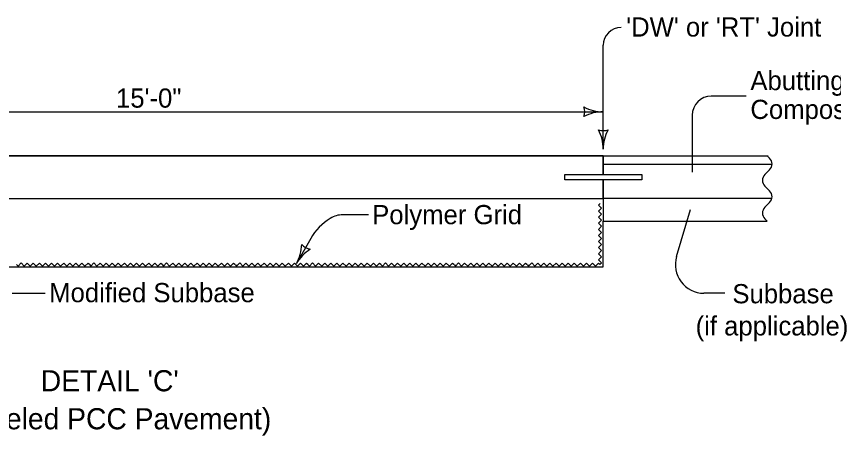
# Model space of a CAD drawing. Extents: x 8925 to 81668, y 4369 to 11918.
# Drawn here: x 14998 to 15849, y 9007 to 9444 of the extents above; entities that cross this region are included whole.
import ezdxf

# ---------------------------------------------------------------- set-up
doc = ezdxf.new("R2010")
doc.units = 0
doc.layers.add('dsnShtPlotShapeBatchPrint', color=7, linetype='Continuous')
doc.layers.add('dsnStdBorder', color=7, linetype='Continuous')

msp = doc.modelspace()

# ---------------------------------------------------------------- linework, layer by layer
at = {"layer": 'dsnStdBorder'}
for p, q in [((15609.52, 9305.72), (15609.52, 9413.92)), ((15758.5, 9360.95), (15722.03, 9360.95)), ((14682.88, 9344.69), (15609.52, 9344.69)), ((15702.23, 9341.15), (15702.23, 9281.87)), ((14693.03, 9298.93), (15609.52, 9298.93)), ((15609.51, 9298.92), (14693.03, 9298.92)), ((15609.51, 9279.43), (15609.51, 9298.92)), ((15609.52, 9298.93), (15609.52, 9279.43)), ((15609.52, 9298.93), (15609.52, 9279.43)), ((15609.52, 9298.93), (15781.23, 9298.93)), ((15782.77, 9296.33), (15780.27, 9298.82)), ((15609.52, 9290.07), (15785.27, 9290.07)), ((15569.42, 9273.86), (15569.42, 9279.43)), ((15569.42, 9279.43), (15609.51, 9279.43)), ((15569.42, 9273.86), (15569.42, 9279.43)), ((15569.42, 9279.43), (15649.61, 9279.43)), ((15649.61, 9279.43), (15649.61, 9273.86)), ((15777.78, 9279.28), (15782.77, 9284.27)), ((15609.51, 9273.86), (15569.42, 9273.86)), ((15649.61, 9273.86), (15569.42, 9273.86)), ((15609.51, 9254.37), (15609.51, 9273.86)), ((15609.52, 9273.86), (15609.52, 9254.38)), ((15780.27, 9264.72), (15777.78, 9267.21)), ((15782.77, 9262.22), (15780.27, 9264.72)), ((14734.1, 9254.38), (15609.52, 9254.38)), ((14734.1, 9254.37), (15609.51, 9254.37)), ((15609.52, 9254.38), (15609.52, 9230.62)), ((15784.26, 9254.38), (15609.52, 9254.38)), ((15777.78, 9245.17), (15782.77, 9250.16)), ((15364.93, 9237.35), (15338.33, 9237.35)), ((15685.87, 9193.82), (15700.45, 9242.79)), ((15609.52, 9218.17), (15609.52, 9230.62)), ((15609.52, 9230.62), (15780.27, 9230.62)), ((15780.27, 9230.62), (15777.78, 9233.11)), ((15609.52, 9183.1), (15609.52, 9218.17)), ((15304.88, 9212.63), (15289.9, 9186.5)), ((14712.58, 9183.1), (15609.52, 9183.1)), ((15028.44, 9155.37), (14993.88, 9155.37)), ((15736.06, 9155.65), (15714.34, 9155.65))]:
    msp.add_line(p, q, dxfattribs=at)
for points in [[(15606.1, 9185.76), (15607.69, 9187.34), (15604.53, 9190.52), (15607.7, 9193.67), (15604.54, 9196.86), (15607.73, 9200.02), (15604.56, 9203.18), (15607.74, 9206.35), (15604.58, 9209.53), (15607.76, 9212.68), (15604.59, 9215.86), (15607.77, 9219.02), (15604.61, 9222.2), (15607.79, 9225.35), (15604.63, 9228.54), (15607.81, 9231.7), (15604.65, 9234.86), (15607.83, 9238.03), (15604.66, 9241.2), (15607.84, 9244.36), (15604.68, 9247.54), (15606.32, 9249.18)], [(14998.48, 9185.58), (15000.06, 9183.99), (15003.24, 9187.15), (15006.4, 9183.97), (15009.58, 9187.13), (15012.74, 9183.95), (15015.91, 9187.11), (15019.07, 9183.93), (15022.25, 9187.1), (15025.4, 9183.92), (15028.59, 9187.08), (15031.75, 9183.9), (15034.92, 9187.06), (15038.08, 9183.89), (15041.26, 9187.05), (15044.42, 9183.87), (15047.59, 9187.03), (15050.75, 9183.85), (15053.92, 9187.02), (15057.08, 9183.84), (15060.27, 9187), (15063.42, 9183.82), (15066.6, 9186.98), (15069.76, 9183.8), (15072.93, 9186.97), (15074.36, 9185.83)], [(15074.35, 9185.58), (15075.93, 9183.99), (15079.11, 9187.15), (15082.26, 9183.97), (15085.45, 9187.13), (15088.61, 9183.95), (15091.78, 9187.11), (15094.94, 9183.93), (15098.12, 9187.1), (15101.27, 9183.92), (15104.46, 9187.08), (15107.62, 9183.9), (15110.79, 9187.06), (15113.94, 9183.89), (15117.13, 9187.05), (15120.29, 9183.87), (15123.46, 9187.03), (15126.62, 9183.85), (15129.79, 9187.02), (15132.95, 9183.84), (15136.14, 9187), (15139.29, 9183.82), (15142.46, 9186.98), (15145.62, 9183.8), (15148.8, 9186.97), (15150.23, 9185.83)], [(15150.04, 9185.58), (15151.61, 9183.99), (15154.8, 9187.15), (15157.95, 9183.97), (15161.13, 9187.13), (15164.29, 9183.95), (15167.46, 9187.11), (15170.62, 9183.93), (15173.81, 9187.1), (15176.96, 9183.92), (15180.14, 9187.08), (15183.3, 9183.9), (15186.48, 9187.06), (15189.63, 9183.89), (15192.81, 9187.05), (15195.97, 9183.87), (15199.14, 9187.03), (15202.3, 9183.85), (15205.48, 9187.02), (15208.64, 9183.84), (15211.82, 9187), (15214.97, 9183.82), (15218.15, 9186.98), (15221.31, 9183.8), (15224.49, 9186.97), (15225.91, 9185.83)], [(15226.16, 9185.58), (15227.74, 9183.99), (15230.92, 9187.15), (15234.08, 9183.97), (15237.26, 9187.13), (15240.42, 9183.95), (15243.59, 9187.11), (15246.75, 9183.93), (15249.93, 9187.1), (15253.08, 9183.92), (15256.27, 9187.08), (15259.43, 9183.9), (15262.6, 9187.06), (15265.76, 9183.89), (15268.94, 9187.05), (15272.1, 9183.87), (15275.27, 9187.03), (15278.43, 9183.85), (15281.6, 9187.02), (15284.76, 9183.84), (15287.95, 9187), (15291.1, 9183.82), (15294.27, 9186.98), (15297.44, 9183.8), (15300.61, 9186.97), (15302.04, 9185.83)], [(15302.02, 9185.58), (15303.6, 9183.99), (15306.78, 9187.15), (15309.94, 9183.97), (15313.12, 9187.13), (15316.28, 9183.95), (15319.45, 9187.11), (15322.61, 9183.93), (15325.79, 9187.1), (15328.95, 9183.92), (15332.13, 9187.08), (15335.29, 9183.9), (15338.46, 9187.06), (15341.62, 9183.89), (15344.8, 9187.05), (15347.96, 9183.87), (15351.13, 9187.03), (15354.29, 9183.85), (15357.46, 9187.02), (15360.63, 9183.84), (15363.81, 9187), (15366.96, 9183.82), (15370.14, 9186.98), (15373.3, 9183.8), (15376.47, 9186.97), (15377.9, 9185.83)], [(15377.97, 9185.58), (15379.54, 9183.99), (15382.73, 9187.15), (15385.88, 9183.97), (15389.06, 9187.13), (15392.22, 9183.95), (15395.39, 9187.11), (15398.55, 9183.93), (15401.73, 9187.1), (15404.89, 9183.92), (15408.07, 9187.08), (15411.23, 9183.9), (15414.41, 9187.06), (15417.56, 9183.89), (15420.74, 9187.05), (15423.9, 9183.87), (15427.07, 9187.03), (15430.23, 9183.85), (15433.41, 9187.02), (15436.57, 9183.84), (15439.75, 9187), (15442.9, 9183.82), (15446.08, 9186.98), (15449.24, 9183.8), (15452.41, 9186.97), (15453.84, 9185.83)], [(15454.09, 9185.58), (15455.67, 9183.99), (15458.85, 9187.15), (15462, 9183.97), (15465.19, 9187.13), (15468.35, 9183.95), (15471.51, 9187.11), (15474.68, 9183.93), (15477.86, 9187.1), (15481.01, 9183.92), (15484.19, 9187.08), (15487.35, 9183.9), (15490.53, 9187.06), (15493.68, 9183.89), (15496.87, 9187.05), (15500.03, 9183.87), (15503.19, 9187.03), (15506.36, 9183.85), (15509.53, 9187.02), (15512.69, 9183.84), (15515.87, 9187), (15519.03, 9183.82), (15522.2, 9186.98), (15525.36, 9183.8), (15528.54, 9186.97), (15529.96, 9185.83)], [(15530.23, 9185.58), (15531.81, 9183.99), (15534.99, 9187.15), (15538.14, 9183.97), (15541.33, 9187.13), (15544.49, 9183.95), (15547.65, 9187.11), (15550.81, 9183.93), (15554, 9187.1), (15557.15, 9183.92), (15560.33, 9187.08), (15563.49, 9183.9), (15566.67, 9187.06), (15569.82, 9183.89), (15573.01, 9187.05), (15576.17, 9183.87), (15579.33, 9187.03), (15582.49, 9183.85), (15585.67, 9187.02), (15588.83, 9183.84), (15592.01, 9187), (15595.17, 9183.82), (15598.34, 9186.98), (15601.5, 9183.8), (15604.68, 9186.97), (15606.1, 9185.83)]]:
    msp.add_lwpolyline(points, dxfattribs=at)
for centre, radius, start, end in [((15628.08, 9413.93), 18.56, 90, 180), ((15722.03, 9341.15), 19.8, 90, 180), ((15573.67, 9344.69), 16.51, 342.26665, 17.73335), ((15609.52, 9387.44), 42.75, 241.92751, 270), ((15573.67, 9344.69), 16.51, 342.26665, 17.73335), ((15609.52, 9387.44), 42.75, 241.92751, 270), ((15609.52, 9301.94), 42.75, 90, 118.07249), ((15609.52, 9301.94), 42.75, 90, 118.07249), ((15609.52, 9341.57), 16.51, 252.26665, 287.73335), ((15566.77, 9305.73), 42.75, 360, 28.07249), ((15609.52, 9341.57), 16.51, 252.26665, 287.73335), ((15566.77, 9305.73), 42.75, 360, 28.07249), ((15652.26, 9305.73), 42.75, 151.92751, 180), ((15652.26, 9305.73), 42.75, 151.92751, 180), ((15776.74, 9290.3), 8.53, 315, 45), ((15783.81, 9273.25), 8.53, 135, 225), ((15776.74, 9256.2), 8.53, 315, 45), ((15783.81, 9239.14), 8.53, 135, 225), ((15338.33, 9212.35), 25, 90, 121.71831), ((15356.41, 9183.09), 59.4, 121.71831, 150.17827), ((15252.81, 9207.75), 42.75, 330.17945, 358.25194), ((15326.99, 9165.24), 42.75, 122.10696, 150.17945), ((15307.72, 9217.59), 16.51, 222.4461, 257.9128), ((15714.34, 9185.35), 29.7, 163.41722, 270)]:
    msp.add_arc(centre, radius, start, end, dxfattribs=at)

# ---------------------------------------------------------------- texts
at = {"layer": 'dsnShtPlotShapeBatchPrint'}
for s, height, p in [("'DW' or 'RT' Joint", 20, (15633.42, 9423.03)), ('Abutting PCC or', 20, (15762.73, 9367.2)), ('15\'-0"', 20, (15102.11, 9348.97)), ('Composite Pavement', 20, (15762.73, 9337.2)), ('Polymer Grid', 20, (15368.88, 9227.56)), ('Modified Subbase', 20, (15032.49, 9146.29)), ('Subbase', 20, (15743.99, 9145.17)), ('(if applicable)', 20, (15705.72, 9111.66)), ('(Doweled PCC Pavement)', 22, (14918.8, 9013.9))]:
    msp.add_text(s, height=height, dxfattribs=at).set_placement(p)
at = {"layer": 'dsnStdBorder'}
msp.add_text("DETAIL 'C'", height=22, dxfattribs=at).set_placement((15023.78, 9053.5))

doc.saveas('drawing.dxf')
